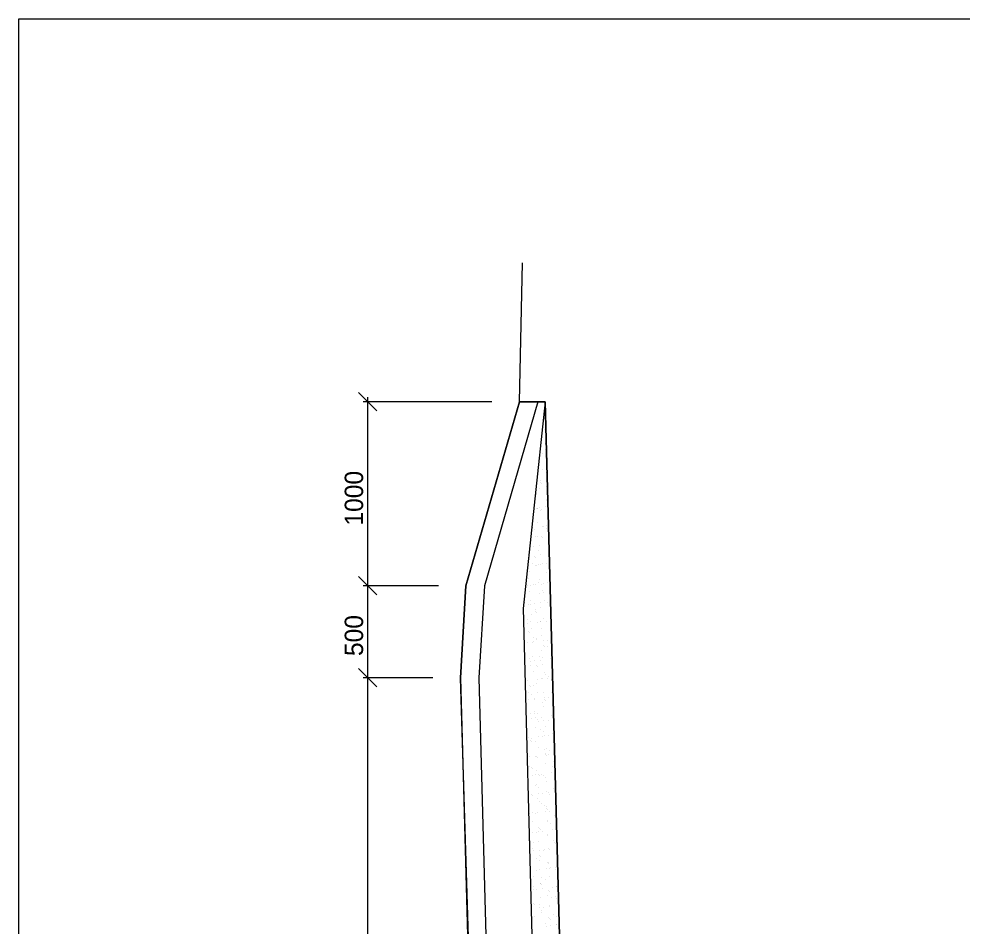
# Model space of a CAD drawing. Extents: x -2363 to 18637, y 14070 to 28920.
# Drawn here: x -2363 to 2762, y 23989 to 28920 of the extents above; entities that cross this region are included whole.
import ezdxf

# ---------------------------------------------------------------- set-up
doc = ezdxf.new("R2010")
doc.units = 0
for name, color, linetype in [('KÓTY', 7, 'Continuous'), ('OBRYS', 7, 'Continuous'), ('SJEZD', 7, 'Continuous'), ('ŠRAFY', 7, 'Continuous')]:
    doc.layers.add(name, color=color, linetype=linetype)

# ---------------------------------------------------------------- blocks, each defined once
blk = doc.blocks.new('_ARCHTICK')
blk.add_lwpolyline([(-0.5, -0.5), (0.5, 0.5)])

msp = doc.modelspace()

# ---------------------------------------------------------------- linework, layer by layer
for p, q in [((-2363.3, 28920.3), (18636.7, 28920.3)), ((-2363.3, 14070.3), (-2363.3, 28920.3))]:
    msp.add_line(p, q)
at = {"layer": 'KÓTY'}
for p, q in [((-468.1, 25814.7), (-468.1, 26864.7)), ((206.8, 26839.7), (-493.1, 26839.7)), ((-84.1, 25839.7), (-493.1, 25839.7)), ((-84.1, 25839.7), (-493.1, 25839.7)), ((-468.1, 25314.7), (-468.1, 25864.7)), ((-114.1, 25339.7), (-493.1, 25339.7)), ((-114.1, 25339.7), (-493.1, 25339.7)), ((-468.1, 22314.7), (-468.1, 25364.7))]:
    msp.add_line(p, q, dxfattribs=at)
at = {"layer": 'OBRYS'}
for p, q in [((356.8, 26839.7), (372.2, 27594.8)), ((65.9, 25839.7), (356.8, 26839.7)), ((495.9, 26839.7), (356.8, 26839.7)), ((649.6, 21092.9), (495.9, 26839.7)), ((35.9, 25339.7), (65.9, 25839.7)), ((146.2, 21839.7), (35.9, 25339.7))]:
    msp.add_line(p, q, dxfattribs=at)
at = {"layer": 'SJEZD'}
for p, q in [((356.8, 26839.7), (372.2, 27594.8)), ((356.8, 26839.7), (65.9, 25839.7)), ((456.8, 26839.7), (165.9, 25839.7)), ((356.8, 26839.7), (495.9, 26839.7)), ((495.9, 26839.7), (375.9, 25715.5)), ((495.9, 26839.7), (649.6, 21092.9)), ((65.9, 25839.7), (35.9, 25339.7)), ((165.9, 25839.7), (135.9, 25338.9)), ((375.9, 25715.5), (493.5, 21318.7)), ((35.9, 25339.7), (116.2, 22339.7)), ((135.9, 25338.9), (216.1, 22342))]:
    msp.add_line(p, q, dxfattribs=at)
at = {"layer": 'ŠRAFY'}
for p, q in [((490.6, 26764.6), (490.6, 26764.6)), ((496.2, 26710.9), (496.2, 26710.9)), ((493.1, 26687.5), (493.1, 26687.5)), ((495.6, 26610.5), (495.6, 26610.5)), ((468.5, 26549.8), (468.5, 26549.8)), ((483.2, 26560), (483.2, 26560)), ((497, 26578.3), (497, 26578.3)), ((500.1, 26549.3), (500.1, 26549.3)), ((498.2, 26533.4), (498.2, 26533.4)), ((480.5, 26472.6), (480.5, 26472.6)), ((500.7, 26456.3), (500.7, 26456.3)), ((501.4, 26475.3), (501.4, 26475.3)), ((468.6, 26410.2), (468.6, 26410.2)), ((470, 26403.1), (470, 26403.1)), ((477.4, 26396.3), (477.4, 26396.3)), ((463.1, 26366.7), (463.1, 26366.7)), ((503.2, 26379.2), (503.2, 26379.2)), ((449.3, 26337.8), (449.3, 26337.8)), ((500.9, 26310), (500.9, 26310)), ((505.7, 26302.2), (505.7, 26302.2)), ((439.2, 26286.1), (439.2, 26286.1)), ((446.6, 26261), (446.6, 26261)), ((451.8, 26260.8), (451.8, 26260.8)), ((455.6, 26259.3), (455.6, 26259.3)), ((467.5, 26263.7), (467.5, 26263.7)), ((472.5, 26248.5), (472.5, 26248.5)), ((474, 26254.2), (474, 26254.2)), ((500, 26268), (500, 26268)), ((508.2, 26225.1), (508.2, 26225.1)), ((429.2, 26155.1), (429.2, 26155.1)), ((435.7, 26144), (435.7, 26144)), ((454.3, 26183.7), (454.3, 26183.7)), ((483.5, 26162.3), (483.5, 26162.3)), ((487.9, 26159.1), (487.9, 26159.1)), ((504.3, 26165), (504.3, 26165)), ((504.8, 26148.4), (504.8, 26148.4)), ((510.8, 26148), (510.8, 26148)), ((440.9, 26109.5), (440.9, 26109.5)), ((456.8, 26106.6), (456.8, 26106.6)), ((475.5, 26107.5), (475.5, 26107.5)), ((482.9, 26100.7), (482.9, 26100.7)), ((412.5, 26048), (412.5, 26048)), ((412.7, 26049.4), (412.7, 26049.4)), ((433.5, 26052.1), (433.5, 26052.1)), ((466.1, 26056.4), (466.1, 26056.4)), ((513.3, 26070.9), (513.3, 26070.9)), ((411.1, 25992.5), (411.1, 25992.5)), ((437.3, 25997.3), (437.3, 25997.3)), ((444.6, 25990.5), (444.6, 25990.5)), ((459.3, 26029.5), (459.3, 26029.5)), ((473.2, 26009.3), (473.2, 26009.3)), ((515.8, 25993.9), (515.8, 25993.9)), ((427.9, 25958.6), (427.9, 25958.6)), ((444.8, 25947.8), (444.8, 25947.8)), ((449.6, 25950.7), (449.6, 25950.7)), ((461.9, 25952.5), (461.9, 25952.5)), ((470.4, 25953.4), (470.4, 25953.4)), ((479.4, 25958.6), (479.4, 25958.6)), ((502.9, 25957.7), (502.9, 25957.7)), ((399, 25887), (399, 25887)), ((406.4, 25880.3), (406.4, 25880.3)), ((413.6, 25915.5), (413.6, 25915.5)), ((505.5, 25909.1), (505.5, 25909.1)), ((518.3, 25916.8), (518.3, 25916.8)), ((519.2, 25922.1), (519.2, 25922.1)), ((399.6, 25840.6), (399.6, 25840.6)), ((416.1, 25838.4), (416.1, 25838.4)), ((432.1, 25844.8), (432.1, 25844.8)), ((441.2, 25848.4), (441.2, 25848.4)), ((460.2, 25858.4), (460.2, 25858.4)), ((464.4, 25875.4), (464.4, 25875.4)), ((477.1, 25847.7), (477.1, 25847.7)), ((486.5, 25852), (486.5, 25852)), ((507.3, 25854.7), (507.3, 25854.7)), ((520.8, 25839.7), (520.8, 25839.7)), ((413.3, 25808.7), (413.3, 25808.7)), ((466.9, 25798.3), (466.9, 25798.3)), ((481, 25811.9), (481, 25811.9)), ((488.4, 25805.2), (488.4, 25805.2)), ((384.8, 25747.3), (384.8, 25747.3)), ((402.9, 25738.2), (402.9, 25738.2)), ((415.7, 25739.1), (415.7, 25739.1)), ((418.7, 25761.3), (418.7, 25761.3)), ((436.5, 25741.8), (436.5, 25741.8)), ((469, 25746.1), (469, 25746.1)), ((492.5, 25758.2), (492.5, 25758.2)), ((509.4, 25747.5), (509.4, 25747.5)), ((523.2, 25773.3), (523.2, 25773.3)), ((523.4, 25762.6), (523.4, 25762.6)), ((523.4, 25753.3), (523.4, 25753.3)), ((421.2, 25684.2), (421.2, 25684.2)), ((442.7, 25701.7), (442.7, 25701.7)), ((445.6, 25708.6), (445.6, 25708.6)), ((450.1, 25694.9), (450.1, 25694.9)), ((469.4, 25721.3), (469.4, 25721.3)), ((525.9, 25685.6), (525.9, 25685.6)), ((398.2, 25633.2), (398.2, 25633.2)), ((400.3, 25657.9), (400.3, 25657.9)), ((417.2, 25647.1), (417.2, 25647.1)), ((452.6, 25640.4), (452.6, 25640.4)), ((471.9, 25644.2), (471.9, 25644.2)), ((473.4, 25643.1), (473.4, 25643.1)), ((484.9, 25663), (484.9, 25663)), ((505.9, 25647.4), (505.9, 25647.4)), ((524.7, 25626.6), (524.7, 25626.6)), ((524.8, 25658.1), (524.8, 25658.1)), ((404.5, 25591.4), (404.5, 25591.4)), ((411.8, 25584.7), (411.8, 25584.7)), ((423.7, 25607.2), (423.7, 25607.2)), ((477.9, 25608.4), (477.9, 25608.4)), ((528.4, 25608.5), (528.4, 25608.5)), ((381.8, 25527.5), (381.8, 25527.5)), ((402.6, 25530.2), (402.6, 25530.2)), ((426.2, 25530.1), (426.2, 25530.1)), ((432.6, 25557.7), (432.6, 25557.7)), ((435.1, 25534.5), (435.1, 25534.5)), ((446.6, 25552.8), (446.6, 25552.8)), ((449.5, 25546.9), (449.5, 25546.9)), ((474.5, 25567.1), (474.5, 25567.1)), ((489.4, 25541.7), (489.4, 25541.7)), ((510.3, 25544.4), (510.3, 25544.4)), ((385.6, 25508), (385.6, 25508)), ((477, 25490), (477, 25490)), ((486.4, 25516.3), (486.4, 25516.3)), ((493.8, 25509.6), (493.8, 25509.6)), ((510.2, 25508.3), (510.2, 25508.3)), ((528.6, 25477.7), (528.6, 25477.7)), ((408.4, 25442.6), (408.4, 25442.6)), ((418.7, 25428.8), (418.7, 25428.8)), ((428.7, 25453), (428.7, 25453)), ((439.5, 25431.5), (439.5, 25431.5)), ((464.9, 25457.5), (464.9, 25457.5)), ((472, 25435.8), (472, 25435.8)), ((481.8, 25446.8), (481.8, 25446.8)), ((526.3, 25443), (526.3, 25443)), ((417.9, 25407.9), (417.9, 25407.9)), ((431.3, 25375.9), (431.3, 25375.9)), ((448.2, 25406.1), (448.2, 25406.1)), ((455.6, 25399.3), (455.6, 25399.3)), ((479.5, 25413), (479.5, 25413)), ((389.5, 25346.4), (389.5, 25346.4)), ((401.2, 25322.9), (401.2, 25322.9)), ((455.5, 25330.1), (455.5, 25330.1)), ((476.4, 25332.8), (476.4, 25332.8)), ((482, 25335.9), (482, 25335.9)), ((490.4, 25367.4), (490.4, 25367.4)), ((497.2, 25357.4), (497.2, 25357.4)), ((508.9, 25337.1), (508.9, 25337.1)), ((514.1, 25346.6), (514.1, 25346.6)), ((530.2, 25331), (530.2, 25331)), ((409.9, 25295.9), (409.9, 25295.9)), ((417.3, 25289.1), (417.3, 25289.1)), ((433.8, 25298.9), (433.8, 25298.9)), ((450.2, 25307.7), (450.2, 25307.7)), ((404.9, 25257), (404.9, 25257)), ((405.6, 25219.9), (405.6, 25219.9)), ((421.8, 25246.2), (421.8, 25246.2)), ((436.3, 25221.8), (436.3, 25221.8)), ((438.1, 25224.2), (438.1, 25224.2)), ((452.1, 25257.2), (452.1, 25257.2)), ((484.5, 25258.8), (484.5, 25258.8)), ((491.9, 25220.7), (491.9, 25220.7)), ((492.4, 25231.4), (492.4, 25231.4)), ((513.2, 25234.1), (513.2, 25234.1)), ((529.5, 25257.2), (529.5, 25257.2)), ((482.5, 25207.5), (482.5, 25207.5)), ((487.1, 25181.7), (487.1, 25181.7)), ((499.3, 25214), (499.3, 25214)), ((534.1, 25182.1), (534.1, 25182.1)), ((413.8, 25147), (413.8, 25147)), ((421.6, 25118.5), (421.6, 25118.5)), ((437.2, 25156.8), (437.2, 25156.8)), ((438.8, 25144.7), (438.8, 25144.7)), ((442.4, 25121.2), (442.4, 25121.2)), ((454.1, 25146.1), (454.1, 25146.1)), ((475, 25125.5), (475, 25125.5)), ((529.3, 25132.7), (529.3, 25132.7)), ((441.3, 25067.7), (441.3, 25067.7)), ((453.7, 25110.5), (453.7, 25110.5)), ((461, 25103.7), (461, 25103.7)), ((489.6, 25104.7), (489.6, 25104.7)), ((495.8, 25071.9), (495.8, 25071.9)), ((514.8, 25107.4), (514.8, 25107.4)), ((404.2, 25012.6), (404.2, 25012.6)), ((458.5, 25019.8), (458.5, 25019.8)), ((469.5, 25056.6), (469.5, 25056.6)), ((479.3, 25022.5), (479.3, 25022.5)), ((486.4, 25045.9), (486.4, 25045.9)), ((492.1, 25027.6), (492.1, 25027.6)), ((511.8, 25026.8), (511.8, 25026.8)), ((535.6, 25035.4), (535.6, 25035.4)), ((543, 25028.6), (543, 25028.6)), ((415.4, 25000.3), (415.4, 25000.3)), ((422.6, 25007), (422.6, 25007)), ((422.8, 24993.5), (422.8, 24993.5)), ((443.9, 24990.6), (443.9, 24990.6)), ((457.6, 24961.6), (457.6, 24961.6)), ((408.5, 24909.6), (408.5, 24909.6)), ((441.1, 24913.9), (441.1, 24913.9)), ((446.4, 24913.5), (446.4, 24913.5)), ((454.9, 24906.8), (454.9, 24906.8)), ((494.6, 24950.5), (494.6, 24950.5)), ((495.4, 24921.1), (495.4, 24921.1)), ((497.4, 24925.1), (497.4, 24925.1)), ((501.9, 24956.5), (501.9, 24956.5)), ((504.7, 24918.4), (504.7, 24918.4)), ((516.2, 24923.8), (516.2, 24923.8)), ((518.7, 24945.7), (518.7, 24945.7)), ((409.6, 24856.1), (409.6, 24856.1)), ((497.1, 24873.5), (497.1, 24873.5)), ((534.2, 24856.3), (534.2, 24856.3)), ((539.5, 24886.5), (539.5, 24886.5)), ((419.3, 24851.4), (419.3, 24851.4)), ((424.6, 24808.2), (424.6, 24808.2)), ((426.5, 24845.3), (426.5, 24845.3)), ((445.4, 24810.9), (445.4, 24810.9)), ((448.9, 24836.4), (448.9, 24836.4)), ((459.1, 24814.9), (459.1, 24814.9)), ((466.5, 24808.1), (466.5, 24808.1)), ((477.9, 24815.2), (477.9, 24815.2)), ((487.2, 24806.7), (487.2, 24806.7)), ((532.3, 24822.4), (532.3, 24822.4)), ((441.9, 24755.9), (441.9, 24755.9)), ((451.4, 24759.4), (451.4, 24759.4)), ((499.7, 24796.4), (499.7, 24796.4)), ((501.3, 24776.3), (501.3, 24776.3)), ((407.1, 24702.3), (407.1, 24702.3)), ((420.9, 24704.7), (420.9, 24704.7)), ((458.8, 24745.2), (458.8, 24745.2)), ((461.5, 24709.5), (461.5, 24709.5)), ((482.3, 24712.2), (482.3, 24712.2)), ((502.2, 24719.3), (502.2, 24719.3)), ((514.8, 24716.5), (514.8, 24716.5)), ((519.5, 24706.5), (519.5, 24706.5)), ((541.1, 24739.8), (541.1, 24739.8)), ((548.5, 24733), (548.5, 24733)), ((428.2, 24697.9), (428.2, 24697.9)), ((453.9, 24682.3), (453.9, 24682.3)), ((463, 24666), (463, 24666)), ((474.2, 24655.8), (474.2, 24655.8)), ((411.5, 24599.3), (411.5, 24599.3)), ((427.2, 24606.1), (427.2, 24606.1)), ((444, 24603.6), (444, 24603.6)), ((456.5, 24605.2), (456.5, 24605.2)), ((491.1, 24645), (491.1, 24645)), ((498.4, 24610.8), (498.4, 24610.8)), ((502.8, 24629.5), (502.8, 24629.5)), ((504.7, 24642.2), (504.7, 24642.2)), ((510.2, 24622.8), (510.2, 24622.8)), ((519.2, 24613.5), (519.2, 24613.5)), ((551.7, 24617.8), (551.7, 24617.8)), ((551.8, 24606.3), (551.8, 24606.3)), ((424.8, 24555.8), (424.8, 24555.8)), ((506.5, 24555.6), (506.5, 24555.6)), ((507.2, 24565.2), (507.2, 24565.2)), ((545, 24590.9), (545, 24590.9)), ((427.6, 24497.9), (427.6, 24497.9)), ((448.4, 24500.6), (448.4, 24500.6)), ((459, 24528.1), (459, 24528.1)), ((459.5, 24505.9), (459.5, 24505.9)), ((464.6, 24519.3), (464.6, 24519.3)), ((472, 24512.6), (472, 24512.6)), ((480.9, 24504.9), (480.9, 24504.9)), ((523.4, 24544.8), (523.4, 24544.8)), ((535.2, 24512), (535.2, 24512)), ((556.1, 24514.8), (556.1, 24514.8)), ((414.2, 24455.2), (414.2, 24455.2)), ((461.5, 24451.1), (461.5, 24451.1)), ((506.8, 24480.7), (506.8, 24480.7)), ((509.7, 24488.1), (509.7, 24488.1)), ((538.8, 24455.4), (538.8, 24455.4)), ((426.3, 24409.1), (426.3, 24409.1)), ((431.1, 24444.5), (431.1, 24444.5)), ((433.7, 24402.3), (433.7, 24402.3)), ((464.4, 24399.2), (464.4, 24399.2)), ((485.3, 24401.9), (485.3, 24401.9)), ((491.8, 24405.8), (491.8, 24405.8)), ((512.3, 24411), (512.3, 24411)), ((517.8, 24406.2), (517.8, 24406.2)), ((546.6, 24444.2), (546.6, 24444.2)), ((553.9, 24437.4), (553.9, 24437.4)), ((555.7, 24444.7), (555.7, 24444.7)), ((446.6, 24355), (446.6, 24355)), ((463.4, 24344.3), (463.4, 24344.3)), ((464, 24374), (464, 24374)), ((468.5, 24370.4), (468.5, 24370.4)), ((447, 24293.3), (447, 24293.3)), ((466.5, 24296.9), (466.5, 24296.9)), ((501.3, 24300.4), (501.3, 24300.4)), ((508.3, 24334), (508.3, 24334)), ((514.8, 24333.9), (514.8, 24333.9)), ((515.7, 24327.2), (515.7, 24327.2)), ((522.1, 24303.2), (522.1, 24303.2)), ((524.1, 24305.6), (524.1, 24305.6)), ((550.5, 24295.3), (550.5, 24295.3)), ((554.7, 24307.5), (554.7, 24307.5)), ((414.5, 24289), (414.5, 24289)), ((415, 24257.4), (415, 24257.4)), ((430.2, 24260.2), (430.2, 24260.2)), ((478.9, 24254.9), (478.9, 24254.9)), ((495.7, 24244.1), (495.7, 24244.1)), ((517.3, 24256.9), (517.3, 24256.9)), ((431.9, 24205.2), (431.9, 24205.2)), ((451.4, 24190.3), (451.4, 24190.3)), ((469.1, 24219.9), (469.1, 24219.9)), ((470, 24223.7), (470, 24223.7)), ((477.4, 24217), (477.4, 24217)), ((483.9, 24194.6), (483.9, 24194.6)), ((538.2, 24201.7), (538.2, 24201.7)), ((556.4, 24205.4), (556.4, 24205.4)), ((559, 24204.5), (559, 24204.5)), ((417.5, 24180.3), (417.5, 24180.3)), ((430.5, 24187.6), (430.5, 24187.6)), ((471.6, 24142.8), (471.6, 24142.8)), ((511.2, 24154.7), (511.2, 24154.7)), ((512.2, 24185.1), (512.2, 24185.1)), ((519.8, 24179.8), (519.8, 24179.8)), ((528, 24144), (528, 24144)), ((552, 24148.6), (552, 24148.6)), ((559.4, 24141.8), (559.4, 24141.8)), ((420, 24103.2), (420, 24103.2)), ((431.8, 24113.5), (431.8, 24113.5)), ((439.2, 24106.7), (439.2, 24106.7)), ((464.2, 24105.1), (464.2, 24105.1)), ((467.4, 24088.9), (467.4, 24088.9)), ((488.2, 24091.6), (488.2, 24091.6)), ((520.8, 24095.9), (520.8, 24095.9)), ((522.3, 24102.7), (522.3, 24102.7)), ((435.8, 24043.6), (435.8, 24043.6)), ((474, 24074.8), (474, 24074.8)), ((474.1, 24065.7), (474.1, 24065.7)), ((513.8, 24038.4), (513.8, 24038.4)), ((543.5, 24054.5), (543.5, 24054.5)), ((560.3, 24043.8), (560.3, 24043.8)), ((422.5, 24026.1), (422.5, 24026.1)), ((496.5, 24004.9), (496.5, 24004.9)), ((504.3, 23990.1), (504.3, 23990.1)), ((521.1, 24031.6), (521.1, 24031.6)), ((524.9, 24025.6), (524.9, 24025.6)), ((525.1, 23992.9), (525.1, 23992.9)), ((555.9, 23999.7), (555.9, 23999.7)), ((557.6, 23997.2), (557.6, 23997.2))]:
    msp.add_line(p, q, dxfattribs=at)

# ---------------------------------------------------------------- block references
at = {"layer": 'KÓTY', "xscale": 100, "yscale": 100}
for p, rotation in [((-468.1, 26839.7), 90), ((-468.1, 25839.7), 90), ((-468.1, 25839.7), -90.00000000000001), ((-468.1, 25339.7), 90), ((-468.1, 25339.7), -90.00000000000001)]:
    msp.add_blockref('_ARCHTICK', p, dxfattribs=dict(at, rotation=rotation))

# ---------------------------------------------------------------- texts
at = {"layer": 'KÓTY'}
for s, p in [('1000', (-493.1, 26166.1)), ('500', (-493.1, 25457.1))]:
    msp.add_text(s, height=100, rotation=90, dxfattribs=at).set_placement(p)

doc.saveas('drawing.dxf')
